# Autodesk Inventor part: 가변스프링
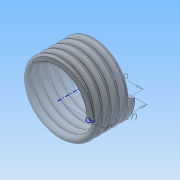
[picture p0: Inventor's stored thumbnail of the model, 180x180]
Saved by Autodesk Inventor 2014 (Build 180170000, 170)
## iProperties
Created: 2020-06
Part Number: 가변스프링
Material: 일반
Document SubType Name: Modeling
Designer: NET
Density: 1 g/cm^3
Appearance: 기본값
Author: NET
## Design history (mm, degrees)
sketch "스케치1"
  geometry: L1 (0, 0)-(10, 0); L2 (10, 0)-(10, 12.7); L3 (10, 12.7)-(0, 12.7); L4 (0, 12.7)-(0, 0); C1 r 1 at (10, 0)
  constraints: 8 end point, 2 parallel, 1 centre point, 1 coincident, 1 horizontal, 1 perpendicular
  dimensions: "d0" = 2 diameter of C1; "d1" = 12.7 distance of L1.end L2.end (derived); "d2" = 20 diameter of L2 L4
feature "코일1" sketch "스케치1" pitch "d3" = 10; turns "d5" = 5; dims "d4" = 12.7 (= d1), "d6" = 0, angle "d7" = 90 deg, angle "d8" = 90 deg, "d9" = 0, "d10" = 0
node "작업 평면1"
sketch "스케치2"
  geometry: L1 (-11, 0)-(-9, 0) reference; 1 further point
  constraints: 1 horizontal alignment
extrude "돌출1" cut sketch "스케치2" distance "d11" = 10; taper "d12" = 0 deg
node "작업 평면2"
sketch "스케치3"
  geometry: L1 (11, 0)-(9, 0) reference; 1 further point
  constraints: 1 horizontal alignment
extrude "돌출2" cut sketch "스케치3" distance "d13" = 10; taper "d14" = 0 deg
node "솔리드1"
node "절단 모서리 투영1"
node "절단 모서리 투영2"
